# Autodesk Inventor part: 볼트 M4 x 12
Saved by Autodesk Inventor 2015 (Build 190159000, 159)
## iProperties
Created: 2025-08
Part Number: 볼트 M4 x 12
Material: 일반
Document SubType Name: Modeling
Designer: user
Density: 1 g/cm^3
Appearance: 기본값
Author: jhkim
Description: 6각머리 태핑 나사
Creation Date: 2025-08-05
Sending System: Autodesk Inventor 2026
Preprocessor: ST-DEVELOPER v20.1
Author: user
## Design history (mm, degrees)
node "볼트 M4 x 121"
body "Solid1"
node "기준1"
